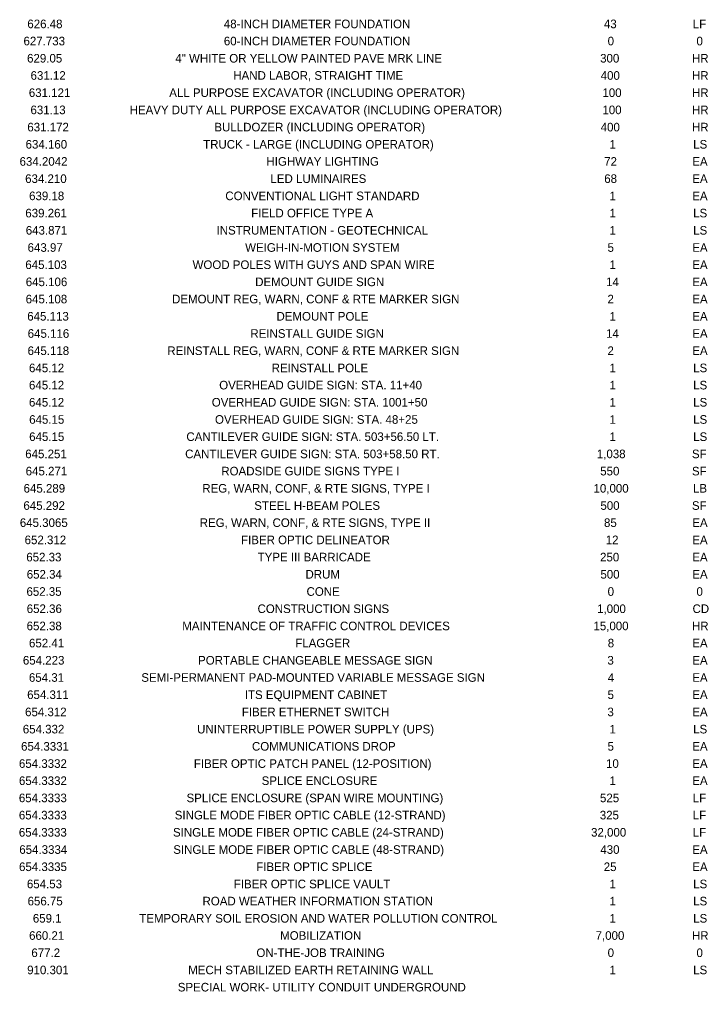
# Model space of a CAD drawing. Extents: x -18.7 to 5.6, y -2.7 to 4.
# Drawn here: x 0.023 to 0.812, y -2.684 to -1.571 of the extents above; entities that cross this region are included whole.
import ezdxf

# ---------------------------------------------------------------- set-up
doc = ezdxf.new("R2010")
doc.units = 0
doc.layers.add('ANNOTATION', color=7, linetype='Continuous')

msp = doc.modelspace()

# ---------------------------------------------------------------- texts
at = {"layer": 'ANNOTATION'}
for s, height, p in [('626.48', 0.00984, (0.0317, -1.5812)), ('48-INCH DIAMETER FOUNDATION', 0.009843, (0.2567, -1.5812)), ('43', 0.00984, (0.6919, -1.5812)), ('LF', 0.00984, (0.7937, -1.5812)), ('627.733', 0.00984, (0.0273, -1.6008)), ('60-INCH DIAMETER FOUNDATION', 0.009843, (0.2567, -1.6008)), ('0', 0.00984, (0.6962, -1.6008)), ('0', 0.00984, (0.7979, -1.6008)), ('629.05', 0.00984, (0.0314, -1.6205)), ('4" WHITE OR YELLOW PAINTED PAVE MRK LINE', 0.009843, (0.2012, -1.6205)), ('300', 0.00984, (0.6876, -1.6205)), ('HR', 0.00984, (0.7927, -1.6205)), ('631.12', 0.00984, (0.0354, -1.6402)), ('HAND LABOR, STRAIGHT TIME', 0.009843, (0.2675, -1.6402)), ('400', 0.00984, (0.6882, -1.6402)), ('HR', 0.00984, (0.7927, -1.6402)), ('631.121', 0.00984, (0.0334, -1.6599)), ('ALL PURPOSE EXCAVATOR (INCLUDING OPERATOR)', 0.009843, (0.1942, -1.6599)), ('100', 0.00984, (0.6902, -1.6599)), ('HR', 0.00984, (0.7927, -1.6599)), ('631.13', 0.00984, (0.0353, -1.6796)), ('HEAVY DUTY ALL PURPOSE EXCAVATOR (INCLUDING OPERATOR)', 0.009843, (0.1488, -1.6796)), ('100', 0.00984, (0.6902, -1.6796)), ('HR', 0.00984, (0.7927, -1.6796)), ('631.172', 0.00984, (0.0317, -1.6993)), ('BULLDOZER (INCLUDING OPERATOR)', 0.009843, (0.2459, -1.6993)), ('400', 0.00984, (0.6882, -1.6993)), ('HR', 0.00984, (0.7927, -1.6993)), ('634.160', 0.00984, (0.0297, -1.719)), ('TRUCK - LARGE (INCLUDING OPERATOR)', 0.009843, (0.233, -1.719)), ('1', 0.00984, (0.6984, -1.719)), ('LS', 0.00984, (0.7941, -1.719)), ('634.2042', 0.00984, (0.0228, -1.7386)), ('HIGHWAY LIGHTING', 0.009843, (0.3055, -1.7386)), ('72', 0.00984, (0.6922, -1.7386)), ('EA', 0.00984, (0.7931, -1.7386)), ('634.210', 0.00984, (0.0292, -1.7583)), ('LED LUMINAIRES', 0.009843, (0.3101, -1.7583)), ('68', 0.00984, (0.6923, -1.7583)), ('EA', 0.00984, (0.7931, -1.7583)), ('639.18', 0.00984, (0.0337, -1.778)), ('CONVENTIONAL LIGHT STANDARD', 0.009843, (0.2584, -1.778)), ('1', 0.00984, (0.6984, -1.778)), ('EA', 0.00984, (0.7931, -1.778)), ('639.261', 0.00984, (0.0294, -1.7977)), ('FIELD OFFICE TYPE A', 0.009843, (0.288, -1.7977)), ('1', 0.00984, (0.6984, -1.7977)), ('LS', 0.00984, (0.7941, -1.7977)), ('643.871', 0.00984, (0.0299, -1.8174)), ('INSTRUMENTATION - GEOTECHNICAL', 0.009843, (0.2484, -1.8174)), ('1', 0.00984, (0.6984, -1.8174)), ('LS', 0.00984, (0.7941, -1.8174)), ('643.97', 0.00984, (0.032, -1.8371)), ('WEIGH-IN-MOTION SYSTEM', 0.009843, (0.2811, -1.8371)), ('5', 0.00984, (0.6961, -1.8371)), ('EA', 0.00984, (0.7931, -1.8371)), ('645.103', 0.00984, (0.0294, -1.8568)), ('WOOD POLES WITH GUYS AND SPAN WIRE', 0.009843, (0.2209, -1.8568)), ('1', 0.00984, (0.6984, -1.8568)), ('EA', 0.00984, (0.7931, -1.8568)), ('645.106', 0.00984, (0.0299, -1.8764)), ('DEMOUNT GUIDE SIGN', 0.009843, (0.2926, -1.8764)), ('14', 0.00984, (0.6944, -1.8764)), ('EA', 0.00984, (0.7931, -1.8764)), ('645.108', 0.00984, (0.0298, -1.8961)), ('DEMOUNT REG, WARN, CONF & RTE MARKER SIGN', 0.009843, (0.1974, -1.8961)), ('2', 0.00984, (0.696, -1.8961)), ('EA', 0.00984, (0.7931, -1.8961)), ('645.113', 0.00984, (0.0316, -1.9158)), ('DEMOUNT POLE', 0.009843, (0.317, -1.9158)), ('1', 0.00984, (0.6984, -1.9158)), ('EA', 0.00984, (0.7931, -1.9158)), ('645.116', 0.00984, (0.0321, -1.9355)), ('REINSTALL GUIDE SIGN', 0.009843, (0.2871, -1.9355)), ('14', 0.00984, (0.6944, -1.9355)), ('EA', 0.00984, (0.7931, -1.9355)), ('645.118', 0.00984, (0.032, -1.9552)), ('REINSTALL REG, WARN, CONF & RTE MARKER SIGN', 0.009843, (0.192, -1.9552)), ('2', 0.00984, (0.696, -1.9552)), ('EA', 0.00984, (0.7931, -1.9552)), ('645.12', 0.00984, (0.0336, -1.9749)), ('REINSTALL POLE', 0.009843, (0.3115, -1.9749)), ('1', 0.00984, (0.6984, -1.9749)), ('LS', 0.00984, (0.7941, -1.9749)), ('645.12', 0.00984, (0.0336, -1.9946)), ('OVERHEAD GUIDE SIGN: STA. 11+40', 0.009843, (0.2514, -1.9946)), ('1', 0.00984, (0.6984, -1.9946)), ('LS', 0.00984, (0.7941, -1.9946)), ('645.12', 0.00984, (0.0336, -2.0142)), ('OVERHEAD GUIDE SIGN: STA. 1001+50', 0.009843, (0.2429, -2.0142)), ('1', 0.00984, (0.6984, -2.0142)), ('LS', 0.00984, (0.7941, -2.0142)), ('645.15', 0.00984, (0.0338, -2.0339)), ('OVERHEAD GUIDE SIGN: STA. 48+25', 0.009843, (0.2466, -2.0339)), ('1', 0.00984, (0.6984, -2.0339)), ('LS', 0.00984, (0.7941, -2.0339)), ('645.15', 0.00984, (0.0338, -2.0536)), ('CANTILEVER GUIDE SIGN: STA. 503+56.50 LT.', 0.009843, (0.2138, -2.0536)), ('1', 0.00984, (0.6984, -2.0536)), ('LS', 0.00984, (0.7941, -2.0536)), ('645.251', 0.00984, (0.0293, -2.0733)), ('CANTILEVER GUIDE SIGN: STA. 503+58.50 RT.', 0.009843, (0.2124, -2.0733)), ('1,038', 0.00984, (0.6838, -2.0733)), ('SF', 0.00984, (0.7927, -2.0733)), ('645.271', 0.00984, (0.0298, -2.093)), ('ROADSIDE GUIDE SIGNS TYPE I ', 0.009843, (0.2538, -2.093)), ('550', 0.00984, (0.6877, -2.093)), ('SF', 0.00984, (0.7927, -2.093)), ('645.289', 0.00984, (0.0274, -2.1127)), ('REG, WARN, CONF, & RTE SIGNS, TYPE I', 0.009843, (0.232, -2.1127)), ('10,000', 0.00984, (0.68, -2.1127)), ('LB', 0.00984, (0.7939, -2.1127)), ('645.292', 0.00984, (0.0272, -2.1324)), ('STEEL H-BEAM POLES', 0.009843, (0.2915, -2.1324)), ('500', 0.00984, (0.6879, -2.1324)), ('SF', 0.00984, (0.7927, -2.1324)), ('645.3065', 0.00984, (0.0231, -2.152)), ('REG, WARN, CONF, & RTE SIGNS, TYPE II', 0.009843, (0.2291, -2.152)), ('85', 0.00984, (0.692, -2.152)), ('EA', 0.00984, (0.7931, -2.152)), ('652.312', 0.00984, (0.0286, -2.1717)), ('FIBER OPTIC DELINEATOR', 0.009843, (0.2764, -2.1717)), ('12', 0.00984, (0.694, -2.1717)), ('EA', 0.00984, (0.7931, -2.1717)), ('652.33', 0.00984, (0.0305, -2.1914)), ('TYPE III BARRICADE', 0.009843, (0.2954, -2.1914)), ('250', 0.00984, (0.6875, -2.1914)), ('EA', 0.00984, (0.7931, -2.1914)), ('652.34', 0.00984, (0.031, -2.2111)), ('DRUM', 0.00984, (0.3502, -2.2111)), ('500', 0.00984, (0.6879, -2.2111)), ('EA', 0.00984, (0.7931, -2.2111)), ('652.35', 0.00984, (0.0307, -2.2308)), ('CONE', 0.00984, (0.3514, -2.2308)), ('0', 0.00984, (0.6962, -2.2308)), ('0', 0.00984, (0.7979, -2.2308)), ('652.36', 0.00984, (0.031, -2.2505)), ('CONSTRUCTION SIGNS', 0.009843, (0.2953, -2.2505)), ('1,000', 0.00984, (0.6841, -2.2505)), ('CD', 0.00984, (0.7934, -2.2505)), ('652.38', 0.00984, (0.0309, -2.2702)), ('MAINTENANCE OF TRAFFIC CONTROL DEVICES', 0.009843, (0.2091, -2.2702)), ('15,000', 0.00984, (0.6799, -2.2702)), ('HR', 0.00984, (0.7927, -2.2702)), ('652.41', 0.00984, (0.0336, -2.2898)), ('FLAGGER', 0.00984, (0.3385, -2.2898)), ('8', 0.00984, (0.6963, -2.2898)), ('EA', 0.00984, (0.7931, -2.2898)), ('654.223', 0.00984, (0.0266, -2.3095)), ('PORTABLE CHANGEABLE MESSAGE SIGN', 0.009843, (0.2272, -2.3095)), ('3', 0.00984, (0.6959, -2.3095)), ('EA', 0.00984, (0.7931, -2.3095)), ('654.31', 0.00984, (0.0335, -2.3292)), ('SEMI-PERMANENT PAD-MOUNTED VARIABLE MESSAGE SIGN', 0.009843, (0.1622, -2.3292)), ('4', 0.00984, (0.6964, -2.3292)), ('EA', 0.00984, (0.7931, -2.3292)), ('654.311', 0.00984, (0.0315, -2.3489)), ('ITS EQUIPMENT CABINET', 0.009843, (0.2807, -2.3489)), ('5', 0.00984, (0.6961, -2.3489)), ('EA', 0.00984, (0.7931, -2.3489)), ('654.312', 0.00984, (0.0291, -2.3686)), ('FIBER ETHERNET SWITCH', 0.009843, (0.2773, -2.3686)), ('3', 0.00984, (0.6959, -2.3686)), ('EA', 0.00984, (0.7931, -2.3686)), ('654.332', 0.00984, (0.0265, -2.3883)), ('UNINTERRUPTIBLE POWER SUPPLY (UPS)', 0.009843, (0.2261, -2.3883)), ('1', 0.00984, (0.6984, -2.3883)), ('LS', 0.00984, (0.7941, -2.3883)), ('654.3331', 0.00984, (0.0245, -2.408)), ('COMMUNICATIONS DROP', 0.009843, (0.2889, -2.408)), ('5', 0.00984, (0.6961, -2.408)), ('EA', 0.00984, (0.7931, -2.408)), ('654.3332', 0.00984, (0.0221, -2.4277)), ('FIBER OPTIC PATCH PANEL (12-POSITION)', 0.009843, (0.2224, -2.4277)), ('10', 0.00984, (0.6943, -2.4277)), ('EA', 0.00984, (0.7931, -2.4277)), ('654.3332', 0.00984, (0.0221, -2.4473)), ('SPLICE ENCLOSURE', 0.009843, (0.3, -2.4473)), ('1', 0.00984, (0.6984, -2.4473)), ('EA', 0.00984, (0.7931, -2.4473)), ('654.3333', 0.00984, (0.022, -2.467)), ('SPLICE ENCLOSURE (SPAN WIRE MOUNTING)', 0.009843, (0.214, -2.467)), ('525', 0.00984, (0.6874, -2.467)), ('LF', 0.00984, (0.7937, -2.467)), ('654.3333', 0.00984, (0.022, -2.4867)), ('SINGLE MODE FIBER OPTIC CABLE (12-STRAND)', 0.009843, (0.2005, -2.4867)), ('325', 0.00984, (0.6872, -2.4867)), ('LF', 0.00984, (0.7937, -2.4867)), ('654.3333', 0.00984, (0.022, -2.5064)), ('SINGLE MODE FIBER OPTIC CABLE (24-STRAND)', 0.009843, (0.1985, -2.5064)), ('32,000', 0.00984, (0.6772, -2.5064)), ('LF', 0.00984, (0.7937, -2.5064)), ('654.3334', 0.00984, (0.0225, -2.5261)), ('SINGLE MODE FIBER OPTIC CABLE (48-STRAND)', 0.009843, (0.1988, -2.5261)), ('430', 0.00984, (0.6878, -2.5261)), ('EA', 0.00984, (0.7931, -2.5261)), ('654.3335', 0.00984, (0.0222, -2.5458)), ('FIBER OPTIC SPLICE', 0.009843, (0.2938, -2.5458)), ('25', 0.00984, (0.6917, -2.5458)), ('EA', 0.00984, (0.7931, -2.5458)), ('654.53', 0.00984, (0.0312, -2.5655)), ('FIBER OPTIC SPLICE VAULT', 0.009843, (0.2681, -2.5655)), ('1', 0.00984, (0.6984, -2.5655)), ('LS', 0.00984, (0.7941, -2.5655)), ('656.75', 0.00984, (0.032, -2.5851)), ('ROAD WEATHER INFORMATION STATION', 0.009843, (0.2323, -2.5851)), ('1', 0.00984, (0.6984, -2.5851)), ('LS', 0.00984, (0.7941, -2.5851)), ('659.1', 0.00984, (0.038, -2.6048)), ('TEMPORARY SOIL EROSION AND WATER POLLUTION CONTROL', 0.009843, (0.1598, -2.6048)), ('1', 0.00984, (0.6984, -2.6048)), ('LS', 0.00984, (0.7941, -2.6048)), ('660.21', 0.00984, (0.0337, -2.6245)), ('MOBILIZATION', 0.009843, (0.3212, -2.6245)), ('7,000', 0.00984, (0.6824, -2.6245)), ('HR', 0.00984, (0.7927, -2.6245)), ('677.2', 0.00984, (0.0363, -2.6442)), ('ON-THE-JOB TRAINING', 0.009843, (0.294, -2.6442)), ('0', 0.00984, (0.6962, -2.6442)), ('0', 0.00984, (0.7979, -2.6442)), ('910.301', 0.00984, (0.0315, -2.6639)), ('MECH STABILIZED EARTH RETAINING WALL', 0.009843, (0.2159, -2.6639)), ('1', 0.00984, (0.6984, -2.6639)), ('LS', 0.00984, (0.7941, -2.6639)), ('SPECIAL WORK- UTILITY CONDUIT UNDERGROUND', 0.009843, (0.204, -2.6836))]:
    msp.add_text(s, height=height, dxfattribs=at).set_placement(p)

doc.saveas('drawing.dxf')
